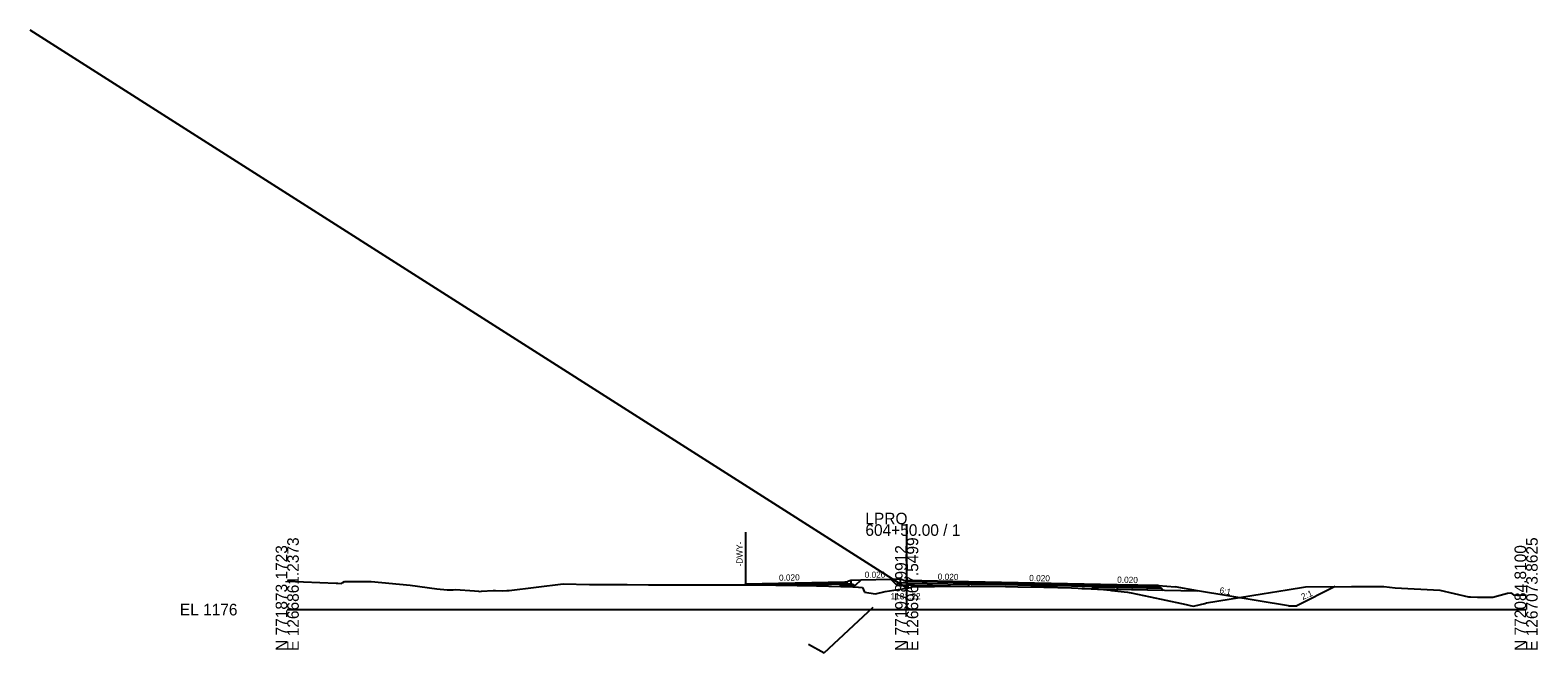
# Model space of a CAD drawing. Extents: x -3833 to 1267678, y -522 to 773248.
# Drawn here: x 937.8 to 1302.8, y 5489.5 to 5640.3 of the extents above; entities that cross this region are included whole.
import ezdxf

# ---------------------------------------------------------------- set-up
doc = ezdxf.new("R2010")
doc.units = 0
for name, color, linetype in [('Exist Cross Section Cell', 7, 'Continuous'), ('Exist XS Center Line Elevation Label', 7, 'Continuous'), ('Exist XS Ground Line', 7, 'Continuous'), ('Prop CMT DNC', 7, 'Continuous'), ('Prop CMT Pvmt Course 1', 7, 'Continuous'), ('Prop CMT Pvmt Course 2', 7, 'Continuous'), ('Prop CMT Pvmt Course 3', 7, 'Continuous'), ('Prop CMT Pvmt Course 4', 7, 'Continuous'), ('Prop CMT Shld Paved Course 1', 7, 'Continuous'), ('Prop CMT Shld Paved Course 2', 7, 'Continuous'), ('Prop CMT Shld Paved Course 4', 7, 'Continuous'), ('Prop CMT Slope Grass', 7, 'Continuous'), ('Prop CMT Subgrade Earthwork', 7, 'Continuous'), ('Prop Conc Curb and Gutter', 7, 'Continuous'), ('Prop Conc Island Cover', 7, 'Continuous'), ('Prop Corridor Mesh Bottom', 7, 'Continuous'), ('Prop XS Ditch Slope Text', 7, 'Continuous'), ('Prop XS Finish Grade', 7, 'Continuous'), ('Prop XS SE Text', 7, 'Continuous'), ('Prop XS Shear Point Element', 7, 'Continuous'), ('Prop XS Shear Point Label', 7, 'Continuous'), ('Scratch_Level_1', 7, 'Continuous'), ('Scratch_Level_5', 7, 'Continuous')]:
    doc.layers.add(name, color=color, linetype=linetype)

msp = doc.modelspace()

# ---------------------------------------------------------------- linework, layer by layer
at = {"layer": 'Exist Cross Section Cell'}
for p, q in [((1150, 5500), (1150, 5520.66)), ((1000, 5500), (1150, 5500)), ((1150, 5500), (1300, 5500))]:
    msp.add_line(p, q, dxfattribs=at)
at = {"layer": 'Exist XS Ground Line'}
for p, q in [((1000, 5506.89), (1011.88, 5506.43)), ((1011.88, 5506.43), (1012.25, 5506.4)), ((1012.25, 5506.4), (1013.13, 5506.35)), ((1013.13, 5506.35), (1013.43, 5506.53)), ((1013.43, 5506.53), (1013.87, 5506.82)), ((1013.87, 5506.82), (1017.66, 5506.79)), ((1017.66, 5506.79), (1020.32, 5506.77)), ((1020.32, 5506.77), (1029.79, 5505.92)), ((1029.79, 5505.92), (1036.25, 5505.04)), ((1053.76, 5504.61), (1066.84, 5506.24)), ((1066.84, 5506.24), (1073.21, 5506.06)), ((1073.21, 5506.06), (1074.4, 5506.07)), ((1074.4, 5506.07), (1075.89, 5506.08)), ((1075.89, 5506.08), (1079.39, 5506.08)), ((1079.39, 5506.08), (1082.32, 5506.07)), ((1082.32, 5506.07), (1087.51, 5506.02)), ((1087.51, 5506.02), (1091.98, 5505.97)), ((1091.98, 5505.97), (1108.88, 5505.98)), ((1108.88, 5505.98), (1111.97, 5506.01)), ((1111.97, 5506.01), (1113.09, 5505.99)), ((1113.09, 5505.99), (1123.47, 5505.85)), ((1123.47, 5505.85), (1125.23, 5505.8)), ((1125.23, 5505.8), (1136.94, 5505.51)), ((1150.97, 5505.38), (1151.43, 5505.57)), ((1151.43, 5505.57), (1153.46, 5505.59)), ((1153.46, 5505.59), (1154.03, 5505.59)), ((1154.03, 5505.59), (1156.74, 5505.59)), ((1156.74, 5505.59), (1165.62, 5505.64)), ((1165.62, 5505.64), (1173.97, 5505.57)), ((1173.97, 5505.57), (1176.89, 5505.54)), ((1176.89, 5505.54), (1183.24, 5505.4)), ((1246.57, 5505.53), (1257.71, 5505.58)), ((1257.71, 5505.58), (1265.51, 5505.6)), ((1265.51, 5505.6), (1268.32, 5505.3)), ((1036.25, 5505.04), (1038.76, 5504.81)), ((1038.76, 5504.81), (1040.2, 5504.81)), ((1040.2, 5504.81), (1040.76, 5504.83)), ((1040.76, 5504.83), (1045.31, 5504.52)), ((1045.31, 5504.52), (1046.31, 5504.43)), ((1046.31, 5504.43), (1046.63, 5504.42)), ((1046.63, 5504.42), (1047.03, 5504.46)), ((1047.03, 5504.46), (1049.85, 5504.6)), ((1049.85, 5504.6), (1050.45, 5504.66)), ((1050.45, 5504.66), (1052.03, 5504.57)), ((1052.03, 5504.57), (1053.2, 5504.63)), ((1053.2, 5504.63), (1053.76, 5504.61)), ((1136.94, 5505.51), (1137.33, 5505.49)), ((1137.33, 5505.49), (1139.27, 5505.38)), ((1139.27, 5505.38), (1139.79, 5504.24)), ((1139.79, 5504.24), (1142.49, 5503.79)), ((1142.49, 5503.79), (1144.82, 5504.38)), ((1144.82, 5504.38), (1150, 5505.22)), ((1150, 5505.22), (1150.97, 5505.38)), ((1183.24, 5505.4), (1189.91, 5505.26)), ((1189.91, 5505.26), (1196.2, 5504.93)), ((1196.2, 5504.93), (1197.68, 5504.85)), ((1197.68, 5504.85), (1199.27, 5504.67)), ((1199.27, 5504.67), (1199.6, 5504.64)), ((1199.6, 5504.64), (1203.47, 5504.2)), ((1203.47, 5504.2), (1203.86, 5504.16)), ((1203.86, 5504.16), (1204.38, 5504.04)), ((1204.38, 5504.04), (1208.99, 5503.09)), ((1208.99, 5503.09), (1216.58, 5501.52)), ((1222.62, 5501.66), (1236.12, 5503.79)), ((1236.12, 5503.79), (1242.17, 5504.77)), ((1242.17, 5504.77), (1246.57, 5505.53)), ((1268.32, 5505.3), (1279.11, 5504.68)), ((1279.11, 5504.68), (1286.05, 5503.09)), ((1286.05, 5503.09), (1286.52, 5503.07)), ((1286.52, 5503.07), (1288.22, 5503.05)), ((1288.22, 5503.05), (1291.48, 5503.02)), ((1291.48, 5503.02), (1291.95, 5503.02)), ((1291.95, 5503.02), (1295.46, 5504.01)), ((1295.46, 5504.01), (1296.27, 5504.05)), ((1296.27, 5504.05), (1296.98, 5503.56)), ((1296.98, 5503.56), (1297.88, 5503.51)), ((1297.88, 5503.51), (1298.25, 5503.53)), ((1298.25, 5503.53), (1300, 5503.6)), ((1216.58, 5501.52), (1216.96, 5501.43)), ((1216.96, 5501.43), (1219.38, 5500.84)), ((1219.38, 5500.84), (1219.74, 5500.92)), ((1219.74, 5500.92), (1222.17, 5501.49)), ((1222.17, 5501.49), (1222.62, 5501.66))]:
    msp.add_line(p, q, dxfattribs=at)
at = {"layer": 'Prop CMT Pvmt Course 1'}
for p, q in [((1111, 5506.24), (1135, 5506.72)), ((1135, 5506.47), (1111, 5506)), ((1111, 5506), (1111, 5506.24)), ((1111, 5506.24), (1111, 5506.24)), ((1135, 5506.72), (1135, 5506.72)), ((1135, 5506.72), (1135, 5506.72)), ((1135, 5506.72), (1135, 5506.47)), ((1135, 5506.47), (1135, 5506.47)), ((1201, 5506), (1165, 5506.72)), ((1165, 5506.72), (1165, 5506.72)), ((1165, 5506.72), (1165, 5506.72)), ((1165, 5506.72), (1165, 5506.47)), ((1165, 5506.47), (1165, 5506.47)), ((1201, 5506), (1195, 5506.12)), ((1195, 5505.87), (1195, 5506.12)), ((1195, 5506.12), (1195, 5506.12)), ((1195, 5506.12), (1195, 5506.12)), ((1195, 5506.12), (1201, 5506)), ((1195, 5505.87), (1201, 5505.75))]:
    msp.add_line(p, q, dxfattribs=at)
at = {"layer": 'Prop CMT Pvmt Course 2'}
for p, q in [((1135, 5506.47), (1135, 5506.47)), ((1135, 5506.47), (1135, 5506.14)), ((1135, 5506.14), (1135, 5506.13)), ((1165, 5506.47), (1149.98, 5506.77)), ((1149.98, 5506.44), (1165, 5506.13)), ((1150, 5506.77), (1150, 5506.77)), ((1150, 5506.77), (1150, 5506.77)), ((1150, 5506.44), (1150, 5506.44)), ((1150, 5506.44), (1150, 5506.44)), ((1165, 5506.13), (1165, 5506.47)), ((1165, 5506.47), (1165, 5506.47)), ((1165, 5506.13), (1165, 5506.13)), ((1195, 5505.54), (1201, 5505.42))]:
    msp.add_line(p, q, dxfattribs=at)
at = {"layer": 'Prop CMT Pvmt Course 3'}
for p, q in [((1135, 5506.13), (1137.01, 5506.18)), ((1135, 5506.13), (1135, 5506.13)), ((1137.01, 5506.18), (1137.01, 5506.18)), ((1137.01, 5506.18), (1137.01, 5506.18)), ((1137.01, 5506.18), (1137.46, 5505.73)), ((1137.3, 5505.89), (1137.3, 5505.89)), ((1147.52, 5506.03), (1147.97, 5506.48)), ((1147.97, 5506.48), (1148.47, 5506.47))]:
    msp.add_line(p, q, dxfattribs=at)
at = {"layer": 'Prop CMT Pvmt Course 4'}
for p, q in [((1134, 5505.59), (1134, 5506.7)), ((1137.46, 5505.73), (1134, 5505.66)), ((1135, 5506.14), (1135, 5506.14)), ((1135, 5506.14), (1135, 5506.13)), ((1150, 5506.44), (1150, 5506.44)), ((1150, 5506.44), (1150, 5506.44)), ((1165, 5506.13), (1165, 5506.13)), ((1165, 5506.13), (1165, 5506.13)), ((1165, 5506.13), (1165, 5505.63)), ((1195, 5505.54), (1195, 5505.08)), ((1138.29, 5505.41), (1138.29, 5505.41))]:
    msp.add_line(p, q, dxfattribs=at)
at = {"layer": 'Prop CMT Shld Paved Course 1'}
for p, q in [((1135, 5506.72), (1135, 5506.72)), ((1135, 5506.72), (1135, 5506.47)), ((1165, 5506.72), (1149.98, 5507.02)), ((1150, 5507.02), (1150, 5507.02)), ((1150, 5507.02), (1150, 5507.02)), ((1150, 5506.77), (1150, 5506.77)), ((1150, 5506.77), (1150, 5506.77)), ((1165, 5506.47), (1165, 5506.72)), ((1165, 5506.72), (1165, 5506.72)), ((1201, 5506), (1201, 5505.75)), ((1211, 5505.8), (1201, 5506)), ((1201, 5505.75), (1211.26, 5505.54)), ((1211.26, 5505.54), (1211, 5505.8))]:
    msp.add_line(p, q, dxfattribs=at)
at = {"layer": 'Prop CMT Shld Paved Course 2'}
for p, q in [((1111, 5506), (1111.97, 5506.01)), ((1111.97, 5506.01), (1111, 5506)), ((1111.97, 5506.01), (1113.09, 5506.03)), ((1111.97, 5506.01), (1111.97, 5506.01)), ((1113.09, 5505.99), (1111.97, 5506.01)), ((1111.97, 5506.01), (1111.97, 5506.01)), ((1111.97, 5506.01), (1111.97, 5506.01)), ((1111.97, 5506.01), (1111.97, 5506.01)), ((1113.09, 5506.03), (1123.47, 5506.24)), ((1113.09, 5506.03), (1113.09, 5506.03)), ((1121.82, 5505.87), (1113.09, 5505.99)), ((1113.09, 5505.99), (1113.09, 5505.99)), ((1123.47, 5505.9), (1121.82, 5505.87)), ((1121.82, 5505.87), (1121.82, 5505.87)), ((1123.47, 5506.24), (1125.23, 5506.27)), ((1123.47, 5506.24), (1123.47, 5506.24)), ((1125.23, 5505.94), (1123.47, 5505.9)), ((1123.47, 5505.9), (1123.47, 5505.9)), ((1125.23, 5506.27), (1135, 5506.47)), ((1125.23, 5506.27), (1125.23, 5506.27)), ((1135, 5506.13), (1125.23, 5505.94)), ((1125.23, 5505.94), (1125.23, 5505.94)), ((1135, 5506.47), (1135, 5506.47)), ((1135, 5506.47), (1135, 5506.47)), ((1135, 5506.47), (1135, 5506.13)), ((1135, 5506.13), (1135, 5506.13)), ((1165, 5506.13), (1165, 5506.47)), ((1165, 5506.47), (1165, 5506.47)), ((1165, 5506.47), (1165.62, 5506.46)), ((1165.62, 5506.12), (1165, 5506.13)), ((1165.62, 5506.46), (1165.62, 5506.46)), ((1165.62, 5506.46), (1165.62, 5506.46)), ((1165.62, 5506.46), (1173.97, 5506.29)), ((1173.97, 5505.96), (1165.62, 5506.12)), ((1165.62, 5506.12), (1165.62, 5506.12)), ((1165.62, 5506.12), (1165.62, 5506.12)), ((1173.97, 5506.29), (1173.97, 5506.29)), ((1173.97, 5506.29), (1176.89, 5506.23)), ((1176.89, 5505.9), (1173.97, 5505.96)), ((1173.97, 5505.96), (1173.97, 5505.96)), ((1176.89, 5506.23), (1183.24, 5506.1)), ((1183.24, 5505.77), (1176.89, 5505.9)), ((1183.24, 5506.1), (1183.24, 5506.1)), ((1183.24, 5506.1), (1189.91, 5505.97)), ((1189.91, 5505.64), (1183.24, 5505.77)), ((1183.24, 5505.77), (1183.24, 5505.77)), ((1189.91, 5505.97), (1189.91, 5505.97)), ((1189.91, 5505.97), (1195, 5505.87)), ((1195, 5505.53), (1189.91, 5505.64)), ((1189.91, 5505.64), (1189.91, 5505.64)), ((1195, 5505.87), (1195, 5505.87)), ((1195, 5505.87), (1195, 5505.87)), ((1195, 5505.87), (1195, 5505.53)), ((1195, 5505.53), (1195, 5505.53)), ((1201, 5505.75), (1201, 5505.42)), ((1211.59, 5505.21), (1211.26, 5505.54)), ((1201, 5505.42), (1211.59, 5505.21))]:
    msp.add_line(p, q, dxfattribs=at)
at = {"layer": 'Prop CMT Shld Paved Course 4'}
for p, q in [((1201, 5505.42), (1201, 5504.96)), ((1201, 5504.96), (1212.06, 5504.74)), ((1211.59, 5505.21), (1211.09, 5505.22)), ((1212.06, 5504.74), (1211.59, 5505.21))]:
    msp.add_line(p, q, dxfattribs=at)
at = {"layer": 'Prop CMT Slope Grass'}
for p, q in [((1136.51, 5507.15), (1138.95, 5507.21)), ((1146.16, 5507.39), (1148.47, 5507.45)), ((1211, 5505.8), (1215, 5505.48)), ((1220.43, 5504.57), (1215, 5505.48))]:
    msp.add_line(p, q, dxfattribs=at)
at = {"layer": 'Prop CMT Subgrade Earthwork'}
for p, q in [((1134, 5505.66), (1137.46, 5505.73)), ((1134, 5505.59), (1134, 5505.66)), ((1138.95, 5507.21), (1137.46, 5505.73)), ((1146.16, 5507.39), (1147.52, 5506.03)), ((1147.52, 5506.03), (1165, 5505.68)), ((1165, 5505.68), (1165, 5505.63)), ((1192.42, 5505.13), (1220.43, 5504.57))]:
    msp.add_line(p, q, dxfattribs=at)
at = {"layer": 'Prop Conc Curb and Gutter'}
for p, q in [((1135, 5506.72), (1135.75, 5506.73)), ((1135, 5506.13), (1135, 5506.72)), ((1135, 5506.72), (1135, 5506.72)), ((1136.51, 5506.17), (1135, 5506.13)), ((1135.75, 5506.9), (1136.51, 5507.15)), ((1135.75, 5506.73), (1135.75, 5506.9)), ((1135.75, 5506.9), (1135.75, 5506.9)), ((1135.75, 5506.73), (1135.75, 5506.73)), ((1136.51, 5507.15), (1136.51, 5507.15)), ((1136.51, 5507.15), (1136.51, 5507.15)), ((1136.51, 5507.15), (1136.51, 5506.17)), ((1136.51, 5506.17), (1136.51, 5506.17)), ((1148.47, 5506.47), (1148.47, 5507.45)), ((1148.47, 5507.45), (1148.47, 5507.45)), ((1148.47, 5507.45), (1148.47, 5507.45)), ((1148.47, 5507.45), (1149.17, 5507.22)), ((1149.98, 5506.43), (1148.47, 5506.47)), ((1148.47, 5506.47), (1148.47, 5506.47)), ((1149.17, 5507.22), (1149.2, 5507.21)), ((1149.2, 5507.21), (1149.22, 5507.2)), ((1149.22, 5507.2), (1149.23, 5507.04)), ((1149.23, 5507.04), (1149.23, 5507.03)), ((1149.23, 5507.03), (1149.59, 5507.03)), ((1149.59, 5507.03), (1149.98, 5507.02)), ((1149.98, 5507.02), (1149.98, 5507.02)), ((1149.98, 5507.02), (1149.98, 5506.43))]:
    msp.add_line(p, q, dxfattribs=at)
at = {"layer": 'Prop Conc Island Cover'}
for p, q in [((1136.51, 5507.15), (1136.51, 5507.15)), ((1136.51, 5506.9), (1136.51, 5506.9))]:
    msp.add_line(p, q, dxfattribs=at)
at = {"layer": 'Prop Corridor Mesh Bottom'}
for p, q in [((1111, 5506.24), (1111, 5506)), ((1135, 5506.72), (1135, 5506.47)), ((1165, 5506.72), (1165, 5506.47))]:
    msp.add_line(p, q, dxfattribs=at)
at = {"layer": 'Prop XS Finish Grade'}
for p, q in [((1136.51, 5507.15), (1136.51, 5507.15)), ((1138.95, 5507.21), (1146.16, 5507.39)), ((1211, 5505.8), (1215, 5505.48)), ((1253.78, 5505.56), (1244.46, 5500.9)), ((1215, 5505.48), (1215, 5505.48)), ((1242.46, 5500.9), (1220.43, 5504.57)), ((1242.46, 5500.9), (1244.46, 5500.9))]:
    msp.add_line(p, q, dxfattribs=at)
at = {"layer": 'Prop XS Shear Point Element'}
msp.add_line((1111, 5518.75), (1111, 5506), dxfattribs=at)
at = {"layer": 'Scratch_Level_1'}
msp.add_line((1150, 5505.22), (937.75, 5640.28), dxfattribs=at)
at = {"layer": 'Scratch_Level_5'}
for p, q in [((1130, 5489.54), (1141.86, 5500.56)), ((1126.22, 5491.64), (1130, 5489.54))]:
    msp.add_line(p, q, dxfattribs=at)

# ---------------------------------------------------------------- texts
at = {"layer": 'Exist Cross Section Cell'}
for s, p in [('604+50.00 / 1', (1140, 5517.86)), ('LPRO', (1140, 5520.66)), ('EL 1176', (974, 5498.6))]:
    msp.add_text(s, height=2.8, dxfattribs=at).set_placement(p)
for s, p in [('E 1266861.2373', (1002.8, 5490)), ('E 1266967.5499', (1152.8, 5490)), ('E 1267073.8625', (1302.8, 5490)), ('N 771873.1723', (1000, 5490)), ('N 771978.9912', (1150, 5490)), ('N 772084.8100', (1300, 5490))]:
    msp.add_text(s, height=2.8, rotation=90, dxfattribs=at).set_placement(p)
at = {"layer": 'Exist XS Center Line Elevation Label'}
msp.add_text('1181.22', height=1.5, dxfattribs=at).set_placement((1146.12, 5502.49))
at = {"layer": 'Prop CMT DNC'}
for p in [(1101, 5506.04), (1111, 5506.24), (1111, 5506.24), (1135, 5506.72), (1135, 5506.72), (1135.75, 5506.73), (1149.23, 5507.03), (1150, 5507.02), (1165, 5506.72), (1165, 5506.72), (1201, 5506), (1201, 5506), (1211, 5505.8), (1242.47, 5504.82)]:
    msp.add_text('X', height=0.00025, dxfattribs=at).set_placement(p)
at = {"layer": 'Prop XS Ditch Slope Text'}
for s, rotation, p in [('6:1', 349.0214, (1225.65, 5504)), ('2:1', 22.8609, (1245.9, 5502.32))]:
    msp.add_text(s, height=1.5, rotation=rotation, dxfattribs=at).set_placement(p)
at = {"layer": 'Prop XS SE Text'}
for rotation, p in [(0.2693, (1139.83, 5507.69)), (1.397, (1119.1, 5506.96)), (358.8542, (1157.51, 5507.24)), (358.8542, (1179.66, 5506.92)), (358.8542, (1200.96, 5506.51))]:
    msp.add_text('0.020', height=1.5, rotation=rotation, dxfattribs=at).set_placement(p)
at = {"layer": 'Prop XS Shear Point Label'}
msp.add_text('-DWY-', height=1.5, rotation=90, dxfattribs=at).set_placement((1110.27, 5510.43))

doc.saveas('drawing.dxf')
